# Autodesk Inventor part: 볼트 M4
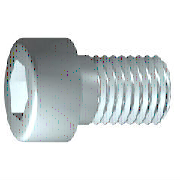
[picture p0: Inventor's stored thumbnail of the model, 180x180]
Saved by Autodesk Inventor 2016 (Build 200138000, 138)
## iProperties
Created: 2012-02
Part Number: 볼트 M4
Material: 스테인리스강
Description: 6각 소켓 머리 캡 나사
Document SubType Name: Modeling
Standard: ISO 4762
Designer: mduedu
Standard Revision: Fourth edition 2004-03-01
Standards Organization: ISO
Language: ko-KR
Size Designation: M4 x 16
Categories: <MemberInstance><Categories><Category DisplayName="조임쇠" InternalName="e4da775c-781d-43d5-af7c-5136215cf5a6" Mnemonic="FSTN"><Category DisplayName="볼트" InternalN
Density: 7.75 g/cm^3
Appearance: 반광택
IsCustomPart: 0
Author: mduedu
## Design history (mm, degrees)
sketch "스케치1"
  geometry: L1 (-1, 0)-(16, 0); L2 (16, 0)-(16, 2); L3 (16, 2)-(1.75, 2); L4 (1.75, 2)-(1.32, 2); L5 (1.32, 2)-(0, 2); L6 (0, 2)-(0, 3.5); L7 (0, 3.5)-(-4, 3.5); L8 (-4, 3.5)-(-4, 1.732); L9 (-4, 1.732)-(-2, 1.732); L10 (-2, 1.732)-(-1, 0); L11 (-8, 0)-(20, 0) reference; L12 (0, -0.7)-(0, 4.2) reference; L13 (1.75, 2)-(0, 2)
  constraints: 22 end point, 6 parallel, 2 collinear, 2 perpendicular, 1 horizontal, 1 point on line
  dimensions: "d1" = 14.25 distance from line of L3.end L2 (= GEL); "d2" = 0.42952 distance of L4.end L3.end (computed from GAL); "d3" = 4 distance between parallel lines of L8 L6 (= KOH); "d4" = 2 distance of L8.end L9.end (= INTI); "d5" = 60 deg angle of L10 L1; "d6" = 4 diameter of L3 L1 (= GD); "d7" = 4 diameter of L5 L1 (= BDM); "d8" = 3.4641 diameter of L9 L1 (= 1.1547 x SW); "d9" = 7 diameter of L7 L1 (= KOD); "d26" = 16 distance between parallel lines of L12 L2 (= NLG)
revolve "본체" sketch "스케치1" stored, may be unused: angle "d10" = 90 deg
sketch "스케치2"
  geometry: L1 (0, -4.9)-(0, 4.9) reference; L2 (-4.9, 0)-(4.9, 0) reference; L3 (1.732, 0)-(0.866, -1.5); L4 (0.866, -1.5)-(-0.866, -1.5); L5 (-0.866, -1.5)-(-1.732, 0); L6 (-1.732, 0)-(-0.866, 1.5); L7 (-0.866, 1.5)-(0.866, 1.5); L8 (0.866, 1.5)-(1.732, 0); 2 further points
  constraints: 12 end point, 1 coincident, 1 horizontal alignment, 1 point on line, 12 other
extrude "슬롯" join sketch "스케치2" stored distance "d11" = 10; taper "d12" = 0 deg
workplane "Work Plane1"
fillet "Fillet2" dims "d30" = 0.1 (= R)
body "Solid1"
fillet "모깎기1" dims "d17" = 0.4 (= RR)
feature "스레드" dims "d13" = 14.25 (= GEL), "d14" = 0
chamfer "모따기1" distance "d15" = 0.42941 (= -0.5 x SPD + 0.5 x GD); stored, may be unused: second distance "d16" = 0.42941 (= GUL), angle "d27" = 45 deg
other parameters: "GD" = 4 [user parameter; used in 2 equation terms], "NLG" = 16 [user parameter; used in 1 equation term], "GEL" = 14.25 [user parameter; used in 2 equation terms], "KOD" = 7 [user parameter; used in 1 equation term], "KOH" = 4 [user parameter; used in 1 equation term], "INTI" = 2 [user parameter; used in 1 equation term], "GAL" = 0.42941 (= 0.61345 x PTC) [user parameter; used in 1 equation term], "GUL" = 0.42941 (= 0.61345 x PTC) [user parameter; used in 1 equation term], "BDM" = 4 (= NND) [user parameter; used in 1 equation term], "SW" = 3 [user parameter; used in 2 equation terms], "RR" = 0.4 [user parameter; used in 1 equation term], "SPD" = 3.14117 (= NND - 1.2269 x PTC) [user parameter; used in 1 equation term], "d19" = 0, "d28" = 0, "d29" = 0, "R" = 0.1 [user parameter; used in 1 equation term], "TOA" = 30 deg [user parameter], "GD1" = 3.14117 (= THREADDIA - 1.2269 x PTC) [user parameter], "THREADDIA" = 4 [user parameter; used in 1 equation term], "FAWI" = 45 deg [user parameter], "TPU" = 14.28571 (computed from PTC) [user parameter], "PTC" = 0.7 [user parameter; used in 5 equation terms], "NND" = 4 [user parameter; used in 2 equation terms], "E0" = 3.465 (= 1.155 x SW) [user parameter]
